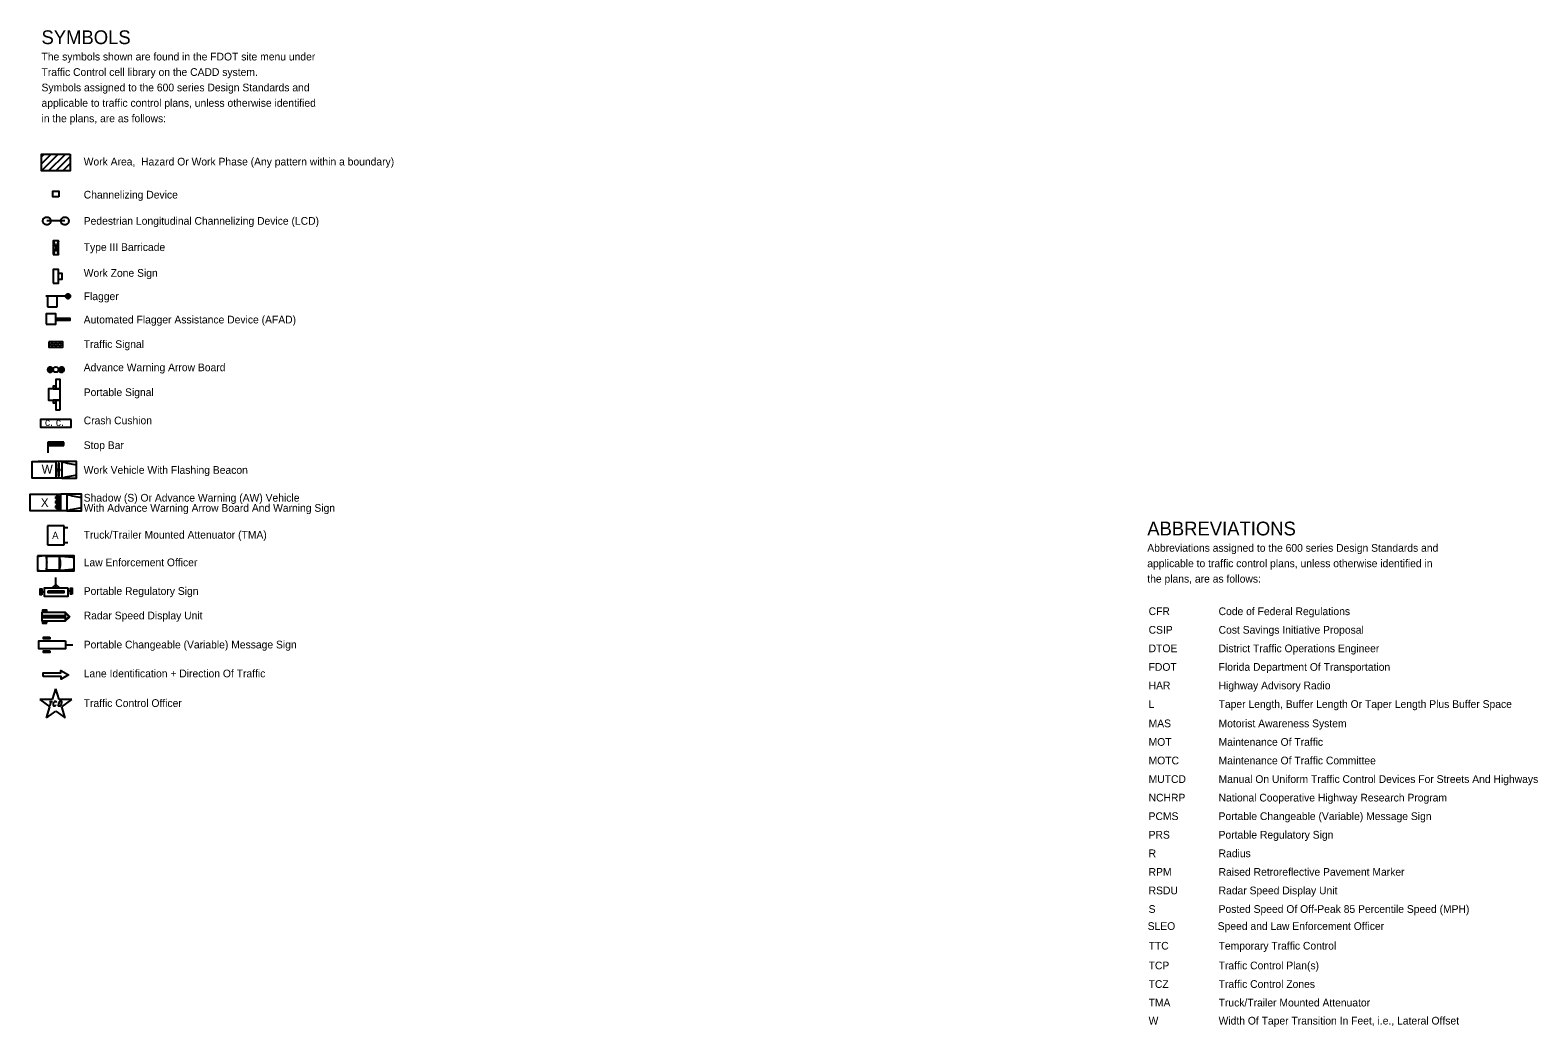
# Model space of a CAD drawing. Extents: x 10000 to 11261, y 10000 to 10478.
# Drawn here: x 10578 to 11261, y 10026 to 10478 of the extents above; entities that cross this region are included whole.
import ezdxf

# ---------------------------------------------------------------- set-up
doc = ezdxf.new("R2010")
doc.units = 0
for name, color, linetype in [('Default', 7, 'Continuous'), ('Dimension', 7, 'Continuous'), ('SupstrConc', 7, 'Continuous'), ('TextMisc', 7, 'Continuous')]:
    doc.layers.add(name, color=color, linetype=linetype)

msp = doc.modelspace()

# ---------------------------------------------------------------- linework, layer by layer
at = {"layer": 'Default'}
msp.add_line((10593.52, 10391.37), (10585.36, 10391.39), dxfattribs=at)
at = {"layer": 'Dimension'}
for p, q in [((10593.18, 10253.04), (10585.7, 10253.04)), ((10585.7, 10253.04), (10585.7, 10244.49)), ((10594.82, 10252.18), (10593.17, 10252.18)), ((10593.18, 10244.49), (10593.18, 10253.04)), ((10585.7, 10244.49), (10593.18, 10244.49)), ((10594.82, 10245.35), (10593.17, 10245.35))]:
    msp.add_line(p, q, dxfattribs=at)
for points in [[(10596.41, 10301.4), (10582.48, 10301.4), (10582.48, 10297.93), (10596.41, 10297.93)], [(10583.68, 10184.73), (10583.68, 10186.38), (10591.78, 10186.38), (10591.78, 10187.54), (10595.21, 10185.55), (10591.79, 10183.59), (10591.79, 10184.73)]]:
    msp.add_lwpolyline(points, close=True, dxfattribs=at)
at = {"layer": 'SupstrConc'}
for points in [[(10586.55, 10173.5), (10587.88, 10173.5)], [(10587.22, 10173.5), (10586.67, 10171.44)], [(10589.8, 10173.02), (10589.77, 10173.21), (10589.62, 10173.4), (10589.47, 10173.5), (10589.1, 10173.5), (10588.87, 10173.4), (10588.64, 10173.21), (10588.48, 10173.02), (10588.3, 10172.72), (10588.17, 10172.22), (10588.19, 10171.93), (10588.24, 10171.73), (10588.38, 10171.54), (10588.38, 10171.54), (10588.91, 10171.44), (10589.13, 10171.54), (10589.37, 10171.73), (10589.51, 10171.93)], [(10590.5, 10171.76), (10590.49, 10171.69), (10590.5, 10171.6), (10590.54, 10171.52), (10590.6, 10171.48), (10590.72, 10171.44), (10591.38, 10171.44), (10591.55, 10171.48), (10591.62, 10171.52), (10591.71, 10171.6), (10591.76, 10171.69), (10591.79, 10171.76), (10592.17, 10173.18), (10592.18, 10173.25), (10592.17, 10173.34), (10592.13, 10173.42), (10592.11, 10173.46), (10591.93, 10173.5), (10591.27, 10173.5), (10591.09, 10173.46), (10591.05, 10173.42), (10590.96, 10173.34), (10590.91, 10173.25), (10590.88, 10173.18), (10590.5, 10171.76)]]:
    msp.add_lwpolyline(points, dxfattribs=at)
at = {"layer": 'TextMisc'}
for p, q in [((10582.92, 10420.51), (10584.12, 10421.71)), ((10582.95, 10414.1), (10590.52, 10421.67)), ((10582.96, 10417.33), (10587.31, 10421.68)), ((10586.18, 10414.11), (10593.78, 10421.72)), ((10589.39, 10414.1), (10595.92, 10420.64)), ((10592.62, 10414.11), (10595.89, 10417.39)), ((10590.69, 10382.42), (10588.19, 10376.17)), ((10588.19, 10382.42), (10590.69, 10376.17)), ((10593.94, 10357.21), (10584.95, 10357.21)), ((10585.71, 10357.21), (10585.71, 10352.47)), ((10585.77, 10357.21), (10585.71, 10357.21)), ((10590.09, 10352.47), (10590.09, 10357.21)), ((10593.92, 10357.36), (10595.98, 10357.36)), ((10593.92, 10357.31), (10595.98, 10357.31)), ((10593.92, 10357.26), (10595.98, 10357.26)), ((10593.92, 10357.21), (10595.98, 10357.21)), ((10593.93, 10357.41), (10595.98, 10357.41)), ((10593.93, 10357.17), (10595.98, 10357.17)), ((10593.93, 10357.11), (10595.97, 10357.11)), ((10593.94, 10357.46), (10595.97, 10357.46)), ((10593.95, 10357.51), (10595.96, 10357.51)), ((10593.95, 10357.07), (10595.96, 10357.07)), ((10593.96, 10357.56), (10595.94, 10357.56)), ((10593.96, 10357.02), (10595.95, 10357.02)), ((10593.97, 10357.61), (10595.93, 10357.61)), ((10593.97, 10356.97), (10595.94, 10356.97)), ((10593.99, 10357.66), (10595.91, 10357.66)), ((10593.99, 10356.92), (10595.92, 10356.92)), ((10594.01, 10356.87), (10595.9, 10356.87)), ((10594.02, 10357.71), (10595.89, 10357.71)), ((10594.03, 10356.82), (10595.87, 10356.82)), ((10594.04, 10357.76), (10595.87, 10357.76)), ((10594.06, 10356.77), (10595.85, 10356.77)), ((10594.07, 10357.81), (10595.84, 10357.81)), ((10594.09, 10356.72), (10595.82, 10356.72)), ((10594.1, 10357.86), (10595.81, 10357.86)), ((10594.12, 10356.67), (10595.78, 10356.67)), ((10594.14, 10357.91), (10595.77, 10357.91)), ((10594.16, 10356.62), (10595.74, 10356.62)), ((10594.18, 10357.96), (10595.73, 10357.96)), ((10594.21, 10356.57), (10595.7, 10356.57)), ((10594.22, 10358.01), (10595.68, 10358.01)), ((10594.26, 10356.52), (10595.65, 10356.52)), ((10594.27, 10358.06), (10595.63, 10358.06)), ((10594.31, 10356.47), (10595.59, 10356.47)), ((10594.34, 10358.11), (10595.57, 10358.11)), ((10594.38, 10356.42), (10595.52, 10356.42)), ((10594.41, 10358.16), (10595.5, 10358.16)), ((10594.47, 10356.37), (10595.44, 10356.37)), ((10594.5, 10358.21), (10595.41, 10358.21)), ((10594.57, 10356.32), (10595.33, 10356.32)), ((10594.62, 10358.26), (10595.29, 10358.26)), ((10594.74, 10356.27), (10595.17, 10356.27)), ((10594.84, 10358.3), (10595.07, 10358.3)), ((10585.71, 10352.47), (10590.09, 10352.47)), ((10585.74, 10291.08), (10585.74, 10289.59)), ((10593.14, 10291.08), (10585.74, 10291.08)), ((10593.11, 10290.97), (10585.74, 10290.97)), ((10593.11, 10290.86), (10585.74, 10290.86)), ((10593.11, 10290.74), (10585.74, 10290.74)), ((10593.13, 10290.63), (10585.74, 10290.63)), ((10593.15, 10290.52), (10585.74, 10290.52)), ((10593.15, 10290.4), (10585.74, 10290.4)), ((10593.13, 10290.29), (10585.74, 10290.29)), ((10593.15, 10290.17), (10585.74, 10290.17)), ((10593.11, 10290.06), (10585.74, 10290.06)), ((10593.15, 10289.95), (10585.74, 10289.95)), ((10593.09, 10289.83), (10585.74, 10289.83)), ((10593.11, 10289.72), (10585.74, 10289.72)), ((10585.75, 10289.59), (10585.75, 10286.18)), ((10585.75, 10289.59), (10593.14, 10289.59)), ((10593.16, 10289.83), (10593.09, 10289.83)), ((10593.14, 10289.59), (10593.14, 10291.08)), ((10589.46, 10282.26), (10581.43, 10282.26)), ((10592.2, 10282.26), (10589.46, 10282.26)), ((10592.21, 10274.68), (10589.47, 10274.68)), ((10594.42, 10267.47), (10591.64, 10267.47)), ((10594.44, 10267.44), (10594.44, 10263.95)), ((10594.42, 10259.89), (10591.64, 10259.89)), ((10587.96, 10225.12), (10589.38, 10226.54)), ((10589.44, 10225.29), (10589.44, 10229.67)), ((10589.46, 10226.55), (10590.89, 10225.12)), ((10583.34, 10223.23), (10584.19, 10223.23)), ((10595.81, 10223.48), (10595.02, 10223.48)), ((10593.79, 10213.87), (10595.74, 10211.92)), ((10593.79, 10213.53), (10595.37, 10211.95)), ((10593.79, 10210.37), (10595.37, 10211.95)), ((10593.8, 10209.98), (10595.74, 10211.92)), ((10593.82, 10199.12), (10596.98, 10199.12)), ((10596.98, 10199.12), (10597.1, 10199.12)), ((10587.88, 10174.37), (10589.44, 10179.17)), ((10591.01, 10174.35), (10589.44, 10179.17)), ((10582.21, 10174.35), (10586.79, 10171.02)), ((10587.83, 10174.35), (10582.21, 10174.35)), ((10585.15, 10165.98), (10586.79, 10171.02)), ((10596.67, 10174.35), (10590.99, 10174.35)), ((10592.09, 10171.02), (10596.67, 10174.35)), ((10593.73, 10165.98), (10592.09, 10171.02)), ((10585.15, 10165.98), (10589.44, 10169.1)), ((10589.44, 10169.1), (10593.73, 10165.98))]:
    msp.add_line(p, q, dxfattribs=at)
for points in [[(10595.93, 10421.71), (10595.93, 10414.1), (10582.95, 10414.1), (10582.95, 10421.71)], [(10590.75, 10402.27), (10588.13, 10402.27), (10588.13, 10404.89), (10590.75, 10404.89)], [(10583.55, 10391.37), (10583.58, 10391.69), (10583.64, 10391.92), (10583.75, 10392.19), (10583.92, 10392.44), (10584.07, 10392.61), (10584.26, 10392.78), (10584.47, 10392.93), (10584.75, 10393.06), (10585.05, 10393.13), (10585.37, 10393.16), (10585.69, 10393.13), (10585.98, 10393.03), (10586.25, 10392.91), (10586.5, 10392.74), (10586.75, 10392.46), (10586.93, 10392.16), (10587.05, 10391.88), (10587.12, 10391.56), (10587.12, 10391.24), (10587.06, 10390.9), (10586.92, 10390.53), (10586.69, 10390.18), (10586.4, 10389.93), (10586.11, 10389.76), (10585.86, 10389.66), (10585.49, 10389.58), (10585.05, 10389.6), (10584.58, 10389.75), (10584.27, 10389.93), (10584.04, 10390.15), (10583.78, 10390.49), (10583.63, 10390.83), (10583.56, 10391.15)], [(10591.74, 10391.37), (10591.77, 10391.68), (10591.82, 10391.92), (10591.93, 10392.18), (10592.1, 10392.43), (10592.25, 10392.61), (10592.44, 10392.78), (10592.66, 10392.92), (10592.94, 10393.06), (10593.23, 10393.13), (10593.55, 10393.15), (10593.87, 10393.12), (10594.16, 10393.03), (10594.43, 10392.9), (10594.68, 10392.74), (10594.93, 10392.45), (10595.11, 10392.16), (10595.23, 10391.87), (10595.3, 10391.55), (10595.3, 10391.24), (10595.24, 10390.9), (10595.11, 10390.53), (10594.87, 10390.18), (10594.58, 10389.93), (10594.29, 10389.76), (10594.05, 10389.66), (10593.67, 10389.58), (10593.23, 10389.6), (10592.76, 10389.74), (10592.46, 10389.93), (10592.22, 10390.14), (10591.97, 10390.49), (10591.82, 10390.83), (10591.75, 10391.14)], [(10585.08, 10344.54), (10589.44, 10344.54), (10589.44, 10349.25), (10585.08, 10349.25)], [(10589.44, 10346.42), (10595.93, 10346.42), (10595.93, 10347.2), (10589.44, 10347.2)], [(10591.42, 10310.1), (10591.42, 10315.18), (10586.12, 10315.18), (10586.12, 10310.1)], [(10589.4, 10315.2), (10589.4, 10316.47), (10588.16, 10316.47), (10588.16, 10315.2)], [(10591.42, 10315.17), (10591.42, 10319.48), (10589.44, 10319.48), (10589.44, 10315.17)], [(10589.4, 10308.82), (10589.4, 10310.09), (10588.16, 10310.09), (10588.16, 10308.82)], [(10591.4, 10305.75), (10591.4, 10310.06), (10589.43, 10310.06), (10589.43, 10305.75)], [(10589.44, 10282.26), (10589.44, 10274.68), (10578.71, 10274.68), (10578.71, 10282.26)], [(10589.45, 10282.24), (10589.45, 10274.66), (10578.72, 10274.66), (10578.72, 10282.24)], [(10590.73, 10279.05), (10590.41, 10278.93), (10590.23, 10278.66), (10590.24, 10278.26), (10590.43, 10278.03), (10590.75, 10277.94), (10591.05, 10278.01), (10591.23, 10278.21), (10591.32, 10278.46), (10591.25, 10278.73), (10591.13, 10278.91), (10590.99, 10279.01)], [(10590.56, 10281.39), (10590.56, 10275.83), (10590.98, 10275.83), (10590.98, 10281.39)], [(10592.2, 10282.26), (10592.2, 10274.71), (10598.85, 10274.71), (10598.85, 10282.26)], [(10592.2, 10282.24), (10592.2, 10274.69), (10598.85, 10274.69), (10598.85, 10282.24)], [(10591.63, 10259.87), (10577.8, 10259.87), (10577.8, 10267.43), (10591.63, 10267.43)], [(10589.83, 10265.3), (10589.83, 10266.53), (10589.76, 10266.5), (10589.67, 10266.45), (10589.52, 10266.4), (10589.42, 10266.32), (10589.3, 10266.14), (10589.27, 10265.87), (10589.34, 10265.62), (10589.47, 10265.44), (10589.61, 10265.32)], [(10590.21, 10266.57), (10590.21, 10260.52), (10590.79, 10260.52), (10590.79, 10266.57)], [(10594.43, 10267.45), (10594.43, 10259.9), (10601.08, 10259.9), (10601.08, 10267.45)], [(10589.78, 10263.23), (10589.78, 10264.46), (10589.72, 10264.44), (10589.62, 10264.38), (10589.48, 10264.33), (10589.37, 10264.26), (10589.26, 10264.07), (10589.22, 10263.8), (10589.3, 10263.56), (10589.43, 10263.37), (10589.57, 10263.26)], [(10589.8, 10261.14), (10589.8, 10262.36), (10589.74, 10262.34), (10589.64, 10262.29), (10589.5, 10262.23), (10589.4, 10262.16), (10589.28, 10261.98), (10589.25, 10261.71), (10589.32, 10261.46), (10589.45, 10261.28), (10589.59, 10261.16)], [(10581.15, 10239.49), (10581.15, 10232.69), (10597.73, 10232.69), (10597.73, 10239.49)], [(10585.3, 10232.98), (10585.3, 10239.32), (10590.89, 10239.32), (10590.89, 10232.98)], [(10583.04, 10221.82), (10582.28, 10221.82), (10582.28, 10224.62), (10583.04, 10224.62)], [(10594.91, 10225.05), (10594.91, 10221.14), (10584.25, 10221.14), (10584.25, 10225.05)], [(10596.79, 10222.06), (10596.03, 10222.06), (10596.03, 10224.86), (10596.79, 10224.86)], [(10585.91, 10223.7), (10593.09, 10223.7), (10593.09, 10222.73), (10585.91, 10222.73)], [(10593.79, 10209.98), (10593.79, 10213.88), (10583.14, 10213.88), (10583.14, 10209.98)], [(10585.29, 10214.26), (10585.29, 10214.83), (10583.34, 10214.83), (10583.34, 10214.26)], [(10583.43, 10212.3), (10583.43, 10211.5), (10593.55, 10211.5), (10593.55, 10212.3)], [(10585.29, 10208.98), (10585.29, 10209.55), (10583.34, 10209.55), (10583.34, 10208.98)], [(10593.86, 10200.94), (10593.86, 10197.39), (10581.78, 10197.39), (10581.78, 10200.94)], [(10586.68, 10202.64), (10586.68, 10201.89), (10583.89, 10201.89), (10583.89, 10202.64)], [(10586.72, 10196.46), (10586.72, 10195.7), (10583.92, 10195.7), (10583.92, 10196.46)]]:
    msp.add_lwpolyline(points, close=True, dxfattribs=at)
for points in [[(10588.19, 10376.17), (10590.69, 10376.17), (10590.69, 10382.42), (10588.19, 10382.42), (10588.19, 10376.17)], [(10588.19, 10363.13), (10590.69, 10363.13), (10590.69, 10369.39), (10588.19, 10369.39), (10588.19, 10363.13)], [(10590.69, 10365.01), (10592.24, 10365.01), (10592.24, 10367.54), (10590.69, 10367.54)], [(10586.31, 10336.59), (10586.31, 10334.08), (10592.57, 10334.08), (10592.57, 10336.59), (10586.31, 10336.59)]]:
    msp.add_lwpolyline(points, dxfattribs=at)
for centre, radius in [((10594.95, 10357.28), 1.03), ((10587.68, 10335.34), 0.601), ((10589.45, 10335.38), 0.601), ((10591.24, 10335.4), 0.601), ((10589.44, 10323.97), 1.2)]:
    msp.add_circle(centre, radius, dxfattribs=at)
for centre, radius, start, end in [((10586.89, 10323.93), 1.2, 248.76421, 246.62419), ((10586.89, 10323.93), 1.09, 248.76421, 246.62419), ((10586.89, 10323.93), 0.977, 248.76421, 246.62419), ((10586.89, 10323.93), 0.863, 248.76421, 246.62419), ((10586.89, 10323.93), 0.749, 248.76421, 246.62419), ((10586.89, 10323.93), 0.635, 248.76421, 246.62419), ((10586.89, 10323.93), 0.522, 248.76421, 246.62419), ((10586.89, 10323.93), 0.408, 248.76421, 246.62419), ((10586.89, 10323.93), 0.294, 248.76421, 246.62419), ((10586.89, 10323.93), 0.18, 248.76421, 246.62419), ((10586.89, 10323.93), 0.0664, 248.76421, 246.62419), ((10592.03, 10323.92), 1.2, 257.5828, 256.88484), ((10592.03, 10323.92), 1.09, 257.5828, 256.88484), ((10592.03, 10323.92), 0.977, 257.5828, 256.88484), ((10592.03, 10323.92), 0.863, 257.5828, 256.88484), ((10592.03, 10323.92), 0.749, 257.5828, 256.88484), ((10592.03, 10323.92), 0.635, 257.5828, 256.88484), ((10592.03, 10323.92), 0.522, 257.5828, 256.88484), ((10592.03, 10323.92), 0.408, 257.5828, 256.88484), ((10592.03, 10323.92), 0.294, 257.5828, 256.88484), ((10592.03, 10323.92), 0.18, 257.5828, 256.88484), ((10592.03, 10323.92), 0.0664, 257.5828, 256.88484), ((10603.05, 10318.15), 37.52, 253.28653, 263.6206), ((10603.1, 10238.77), 37.52, 96.3794, 106.71347), ((10605.24, 10303.35), 37.52, 253.28653, 263.6206), ((10589.91, 10264.03), 0.613, 87.46345, 88.47743), ((10605.28, 10223.97), 37.52, 96.3794, 106.71347), ((10585.28, 10211.75), 27.71, 90.13964, 98.75148), ((11090.07, 10272.4), 506.06, 183.73137, 184.07759), ((10583.5, 10236.14), 8.08, 336.61115, 23.38885), ((10586.81, 10151.93), 87.43, 82.89868, 87.263), ((10585.3, 10260.38), 27.71, 261.24852, 269.86036), ((11090.04, 10199.81), 506.06, 175.92241, 176.26863), ((10590.86, 10272.81), 39.8, 270.00423, 279.93894)]:
    msp.add_arc(centre, radius, start, end, dxfattribs=at)

# ---------------------------------------------------------------- texts
at = {"layer": 'SupstrConc'}
for s, height, p in [('SYMBOLS', 6.25, (10582.95, 10471.56)), ('The symbols shown are found in the FDOT site menu under', 3.5, (10582.95, 10464.15)), ('Traffic Control cell library on the CADD system.', 3.5, (10582.95, 10457.15)), ('Symbols assigned to the 600 series Design Standards and', 3.5, (10582.95, 10450.15)), ('applicable to traffic control plans, unless otherwise identified', 3.5, (10582.95, 10443.15)), ('in the plans, are as follows:', 3.5, (10582.95, 10436.15)), ('Work Area,  Hazard Or Work Phase (Any pattern within a boundary)', 3.5, (10602.08, 10416.53)), ('Channelizing Device', 3.5, (10602.08, 10401.54)), ('Pedestrian Longitudinal Channelizing Device (LCD)', 3.5, (10602.08, 10389.65)), ('Type III Barricade', 3.5, (10602.08, 10377.77)), ('Work Zone Sign', 3.5, (10602.08, 10366.04)), ('Flagger', 3.5, (10602.08, 10355.46)), ('Automated Flagger Assistance Device (AFAD)', 3.5, (10602.08, 10344.89)), ('Traffic Signal', 3.5, (10602.08, 10333.77)), ('Advance Warning Arrow Board', 3.5, (10602.08, 10323.23)), ('Portable Signal', 3.5, (10602.08, 10311.95)), ('c. c.', 3.5, (10584.5, 10298.41)), ('Crash Cushion', 3.5, (10602.08, 10299.16)), ('Stop Bar', 3.5, (10602.08, 10287.94)), ('Work Vehicle With Flashing Beacon', 3.5, (10602.08, 10276.7)), ('Shadow (S) Or Advance Warning (AW) Vehicle', 3.5, (10602.08, 10264.1)), ('With Advance Warning Arrow Board And Warning Sign ', 3.5, (10602.08, 10259.49)), ('ABBREVIATIONS', 6.25, (11084.18, 10248.77)), ('A', 3.19, (10587.79, 10247.21)), ('Truck/Trailer Mounted Attenuator (TMA)', 3.5, (10602.08, 10247.33)), ('Abbreviations assigned to the 600 series Design Standards and ', 3.5, (11084.18, 10241.36)), ('Law Enforcement Officer', 3.5, (10602.08, 10234.79)), ('applicable to traffic control plans, unless otherwise identified in ', 3.5, (11084.18, 10234.36)), ('the plans, are as follows:', 3.5, (11084.18, 10227.36)), ('Portable Regulatory Sign', 3.5, (10602.08, 10221.8)), ('Radar Speed Display Unit', 3.5, (10602.08, 10210.7)), ('CFR', 3.5, (11084.79, 10212.64)), ('Code of Federal Regulations', 3.5, (11116.51, 10212.62)), ('CSIP', 3.5, (11084.79, 10204.22)), ('Cost Savings Initiative Proposal', 3.5, (11116.51, 10204.2)), ('Portable Changeable (Variable) Message Sign', 3.5, (10602.08, 10197.52)), ('DTOE', 3.5, (11084.79, 10195.8)), ('District Traffic Operations Engineer', 3.5, (11116.51, 10195.8)), ('FDOT', 3.5, (11084.79, 10187.38)), ('Florida Department Of Transportation', 3.5, (11116.51, 10187.38)), ('Lane Identification + Direction Of Traffic', 3.5, (10602.08, 10184.41)), ('HAR', 3.5, (11084.79, 10178.96)), ('Highway Advisory Radio', 3.5, (11116.51, 10178.96)), ('Traffic Control Officer', 3.5, (10602.08, 10170.98)), ('L', 3.5, (11084.79, 10170.54)), ('Taper Length, Buffer Length Or Taper Length Plus Buffer Space', 3.5, (11116.51, 10170.54)), ('MAS', 3.5, (11084.79, 10161.78)), ('Motorist Awareness System', 3.5, (11116.51, 10161.78)), ('MOT', 3.5, (11084.79, 10153.36)), ('Maintenance Of Traffic ', 3.5, (11116.51, 10153.36)), ('MOTC', 3.5, (11084.79, 10144.94)), ('Maintenance Of Traffic Committee ', 3.5, (11116.51, 10144.94)), ('MUTCD', 3.5, (11084.79, 10136.52)), ('Manual On Uniform Traffic Control Devices For Streets And Highways', 3.5, (11116.51, 10136.52)), ('NCHRP ', 3.5, (11084.79, 10128.11)), ('National Cooperative Highway Research Program', 3.5, (11116.51, 10128.11)), ('PCMS', 3.5, (11084.79, 10119.69)), ('Portable Changeable (Variable) Message Sign', 3.5, (11116.51, 10119.69)), ('PRS', 3.5, (11084.79, 10111.27)), ('Portable Regulatory Sign', 3.5, (11116.51, 10111.27)), ('R', 3.5, (11084.79, 10102.85)), ('Radius', 3.5, (11116.51, 10102.85)), ('RPM', 3.5, (11084.79, 10094.43)), ('Raised Retroreflective Pavement Marker', 3.5, (11116.51, 10094.43)), ('RSDU', 3.5, (11084.79, 10086.01)), ('Radar Speed Display Unit', 3.5, (11116.51, 10086.01)), ('S', 3.5, (11084.79, 10077.59)), ('Posted Speed Of Off-Peak 85 Percentile Speed (MPH)', 3.5, (11116.51, 10077.59)), ('SLEO', 3.5, (11084.36, 10069.86)), ('Speed and Law Enforcement Officer', 3.5, (11116.09, 10069.86)), ('TTC', 3.5, (11084.79, 10060.94)), ('Temporary Traffic Control', 3.5, (11116.51, 10060.94)), ('TCP', 3.5, (11084.79, 10051.99)), ('Traffic Control Plan(s)', 3.5, (11116.51, 10051.99)), ('TCZ', 3.5, (11084.79, 10043.57)), ('Traffic Control Zones', 3.5, (11116.51, 10043.57)), ('TMA', 3.5, (11084.79, 10035.15)), ('Truck/Trailer Mounted Attenuator', 3.5, (11116.51, 10035.15)), ('W', 3.5, (11084.79, 10026.96)), ('Width Of Taper Transition In Feet, i.e., Lateral Offset', 3.5, (11116.51, 10026.96))]:
    msp.add_text(s, height=height, dxfattribs=at).set_placement(p)
at = {"layer": 'TextMisc'}
for s, p in [('W', (10583.02, 10276.81)), ('X', (10582.61, 10261.63))]:
    msp.add_text(s, height=3.98, dxfattribs=at).set_placement(p)

doc.saveas('drawing.dxf')
